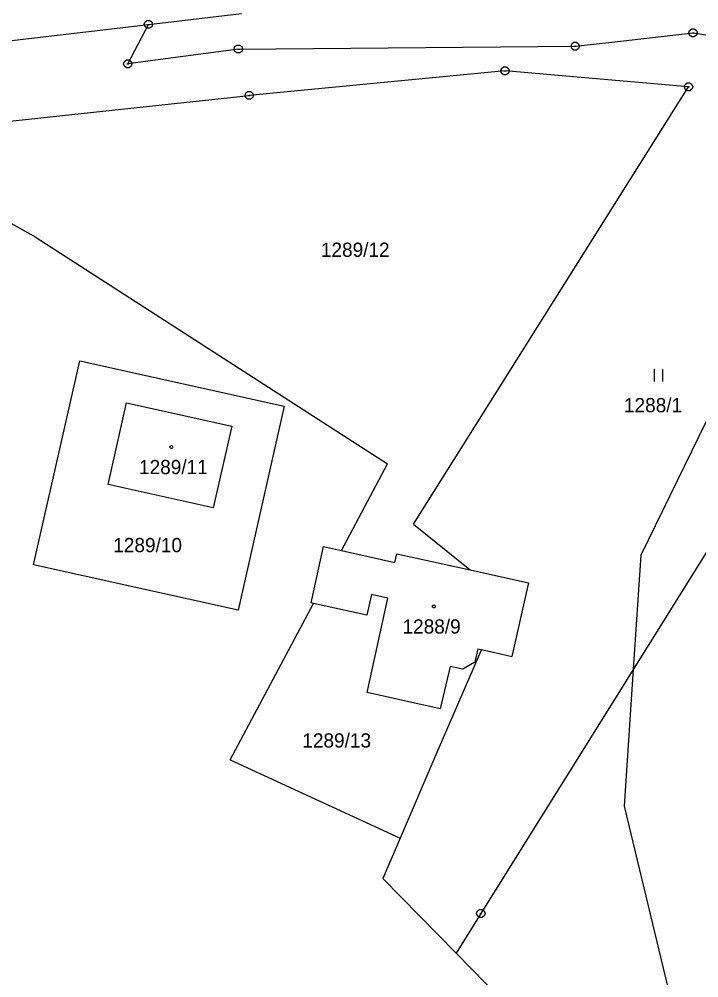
# Model space of a CAD drawing. Extents: x -806774 to -803680, y -1151731 to -1150053.
# Drawn here: x -804399.3 to -804318.1, y -1150598.5 to -1150483.9 of the extents above; entities that cross this region are included whole.
import ezdxf

# ---------------------------------------------------------------- set-up
doc = ezdxf.new("R2010")
doc.units = 0
for name, color, linetype in [('1', 7, 'Continuous'), ('11', 7, 'Continuous'), ('12', 7, 'Continuous'), ('2', 7, 'Continuous'), ('3', 7, 'Continuous'), ('5', 7, 'Continuous'), ('8', 7, 'Continuous')]:
    doc.layers.add(name, color=color, linetype=linetype)

msp = doc.modelspace()

# ---------------------------------------------------------------- linework, layer by layer
at = {"layer": '1'}
for p, q in [((-804383.87, -1150484.55), (-804372.75, -1150483.24)), ((-804413.66, -1150488.07), (-804383.87, -1150484.55)), ((-804386.34, -1150489.27), (-804383.87, -1150484.55)), ((-804328.48, -1150486.67), (-804318.77, -1150485.56)), ((-804318.77, -1150485.56), (-804301.09, -1150488.42)), ((-804332.85, -1150487.17), (-804328.48, -1150486.67)), ((-804373.12, -1150487.5), (-804386.34, -1150489.27)), ((-804373.12, -1150487.5), (-804332.85, -1150487.17)), ((-804341.25, -1150490.12), (-804371.82, -1150493.04)), ((-804330.8, -1150491.03), (-804341.25, -1150490.12)), ((-804319.3, -1150492.03), (-804330.8, -1150491.03)), ((-804352.2, -1150544.3), (-804319.3, -1150492.03)), ((-804282.73, -1150492.43), (-804344.13, -1150590.85)), ((-804389.32, -1150494.92), (-804371.82, -1150493.04)), ((-804418.66, -1150498.07), (-804389.32, -1150494.92)), ((-804397.29, -1150510.02), (-804418.66, -1150498.07)), ((-804397.29, -1150510.02), (-804355.28, -1150537.09)), ((-804397.61, -1150549.18), (-804392.08, -1150524.79)), ((-804392.08, -1150524.79), (-804367.66, -1150530.19)), ((-804388.69, -1150539.57), (-804386.51, -1150529.81)), ((-804386.51, -1150529.81), (-804373.89, -1150532.57)), ((-804367.66, -1150530.19), (-804373.16, -1150554.57)), ((-804373.89, -1150532.57), (-804376.12, -1150542.34)), ((-804360.79, -1150547.46), (-804355.28, -1150537.09)), ((-804376.12, -1150542.34), (-804388.69, -1150539.57)), ((-804352.2, -1150544.3), (-804345.42, -1150549.78)), ((-804364.41, -1150553.72), (-804362.93, -1150546.98)), ((-804362.93, -1150546.98), (-804360.79, -1150547.46)), ((-804360.79, -1150547.46), (-804354.4, -1150548.88)), ((-804354.4, -1150548.88), (-804354.17, -1150547.83)), ((-804354.17, -1150547.83), (-804345.42, -1150549.78)), ((-804373.16, -1150554.57), (-804397.61, -1150549.18)), ((-804345.42, -1150549.78), (-804338.45, -1150551.33)), ((-804338.45, -1150551.33), (-804338.96, -1150553.59)), ((-804357.21, -1150552.7), (-804357.78, -1150555.19)), ((-804357.73, -1150564.42), (-804355.25, -1150553.13)), ((-804355.25, -1150553.13), (-804357.21, -1150552.7)), ((-804374.09, -1150572.48), (-804364.15, -1150553.78)), ((-804364.15, -1150553.78), (-804364.41, -1150553.72)), ((-804357.78, -1150555.19), (-804364.15, -1150553.78)), ((-804338.96, -1150553.59), (-804340.43, -1150560.12)), ((-804344.48, -1150559.2), (-804344.87, -1150560.8)), ((-804344.48, -1150559.2), (-804344.07, -1150559.29)), ((-804344.07, -1150559.29), (-804349.26, -1150571.32)), ((-804344.07, -1150559.29), (-804342.48, -1150559.65)), ((-804342.48, -1150559.65), (-804340.43, -1150560.12)), ((-804347.82, -1150561.33), (-804348.99, -1150566.39)), ((-804346.3, -1150561.65), (-804347.82, -1150561.33)), ((-804344.87, -1150560.8), (-804346.3, -1150561.65)), ((-804348.99, -1150566.39), (-804357.73, -1150564.42)), ((-804349.26, -1150571.32), (-804353.79, -1150581.83)), ((-804374.09, -1150572.48), (-804353.79, -1150581.83)), ((-804353.79, -1150581.83), (-804355.87, -1150586.66)), ((-804355.87, -1150586.66), (-804347.09, -1150595.59)), ((-804344.13, -1150590.85), (-804347.09, -1150595.59)), ((-804347.09, -1150595.59), (-804341.03, -1150601.74))]:
    msp.add_line(p, q, dxfattribs=at)
at = {"layer": '11'}
msp.add_lwpolyline([(-804201.49, -1150551.96), (-804209.11, -1150543.47), (-804210.39, -1150542.04), (-804212.51, -1150539.67), (-804218.5, -1150533), (-804222.87, -1150529.61), (-804225.18, -1150527.81), (-804228.47, -1150525.26), (-804229.6, -1150524.38), (-804232.27, -1150522.31), (-804232.51, -1150522.12), (-804256.88, -1150503.2), (-804257.64, -1150502.61), (-804261, -1150500), (-804264.52, -1150499.82), (-804286.63, -1150498.67), (-804290, -1150498.5), (-804315.5, -1150528.5), (-804325, -1150548), (-804325.91, -1150561.64), (-804327, -1150578), (-804320.5, -1150605)], dxfattribs=at)
at = {"layer": '12'}
for p, q in [((-804388.69, -1150539.57), (-804386.51, -1150529.81)), ((-804386.51, -1150529.81), (-804373.89, -1150532.57)), ((-804373.89, -1150532.57), (-804376.12, -1150542.34)), ((-804376.12, -1150542.34), (-804388.69, -1150539.57)), ((-804364.41, -1150553.72), (-804362.93, -1150546.98)), ((-804362.93, -1150546.98), (-804360.79, -1150547.46)), ((-804360.79, -1150547.46), (-804354.4, -1150548.88)), ((-804354.4, -1150548.88), (-804354.17, -1150547.83)), ((-804354.17, -1150547.83), (-804345.42, -1150549.78)), ((-804345.42, -1150549.78), (-804338.45, -1150551.33)), ((-804338.45, -1150551.33), (-804338.96, -1150553.59)), ((-804357.21, -1150552.7), (-804357.78, -1150555.19)), ((-804357.73, -1150564.42), (-804355.25, -1150553.13)), ((-804355.25, -1150553.13), (-804357.21, -1150552.7)), ((-804364.15, -1150553.78), (-804364.41, -1150553.72)), ((-804357.78, -1150555.19), (-804364.15, -1150553.78)), ((-804338.96, -1150553.59), (-804340.43, -1150560.12)), ((-804344.48, -1150559.2), (-804344.87, -1150560.8)), ((-804344.48, -1150559.2), (-804344.07, -1150559.29)), ((-804344.07, -1150559.29), (-804342.48, -1150559.65)), ((-804342.48, -1150559.65), (-804340.43, -1150560.12)), ((-804347.82, -1150561.33), (-804348.99, -1150566.39)), ((-804346.3, -1150561.65), (-804347.82, -1150561.33)), ((-804344.87, -1150560.8), (-804346.3, -1150561.65)), ((-804348.99, -1150566.39), (-804357.73, -1150564.42))]:
    msp.add_line(p, q, dxfattribs=at)
at = {"layer": '3'}
for p, q in [((-804323.4, -1150525.76), (-804323.4, -1150527.26)), ((-804322.4, -1150527.26), (-804322.4, -1150525.76))]:
    msp.add_line(p, q, dxfattribs=at)
at = {"layer": '5'}
for points in [[(-804381.13, -1150534.91), (-804381.03, -1150534.93), (-804380.98, -1150535.02), (-804380.96, -1150535.08), (-804380.98, -1150535.17), (-804381.06, -1150535.24), (-804381.13, -1150535.25), (-804381.22, -1150535.22), (-804381.28, -1150535.16), (-804381.3, -1150535.08), (-804381.28, -1150534.99), (-804381.2, -1150534.92)], [(-804349.76, -1150553.97), (-804349.66, -1150553.99), (-804349.61, -1150554.08), (-804349.59, -1150554.14), (-804349.61, -1150554.23), (-804349.69, -1150554.3), (-804349.76, -1150554.31), (-804349.85, -1150554.28), (-804349.91, -1150554.22), (-804349.93, -1150554.14), (-804349.91, -1150554.05), (-804349.83, -1150553.98)]]:
    msp.add_lwpolyline(points, close=True, dxfattribs=at)
at = {"layer": '8'}
for p, q in [((-804383.99, -1150484.55), (-804383.75, -1150484.55)), ((-804318.89, -1150485.56), (-804318.65, -1150485.56)), ((-804373.24, -1150487.5), (-804373, -1150487.5)), ((-804332.97, -1150487.17), (-804332.73, -1150487.17)), ((-804386.46, -1150489.27), (-804386.22, -1150489.27)), ((-804341.37, -1150490.12), (-804341.13, -1150490.12)), ((-804319.42, -1150492.03), (-804319.18, -1150492.03)), ((-804371.94, -1150493.04), (-804371.7, -1150493.04)), ((-804344.25, -1150590.85), (-804344.01, -1150590.85))]:
    msp.add_line(p, q, dxfattribs=at)
for points in [[(-804383.72, -1150484.07), (-804383.47, -1150484.25), (-804383.37, -1150484.54), (-804383.47, -1150484.83), (-804383.72, -1150485.01), (-804384.03, -1150485.01), (-804384.28, -1150484.83), (-804384.38, -1150484.54), (-804384.28, -1150484.25), (-804384.03, -1150484.07)], [(-804318.62, -1150485.08), (-804318.37, -1150485.26), (-804318.27, -1150485.55), (-804318.37, -1150485.84), (-804318.62, -1150486.02), (-804318.93, -1150486.02), (-804319.18, -1150485.84), (-804319.28, -1150485.55), (-804319.18, -1150485.26), (-804318.93, -1150485.08)], [(-804372.97, -1150487.02), (-804372.72, -1150487.2), (-804372.62, -1150487.49), (-804372.72, -1150487.78), (-804372.97, -1150487.96), (-804373.28, -1150487.96), (-804373.53, -1150487.78), (-804373.63, -1150487.49), (-804373.53, -1150487.2), (-804373.28, -1150487.02)], [(-804332.7, -1150486.69), (-804332.45, -1150486.87), (-804332.35, -1150487.16), (-804332.45, -1150487.45), (-804332.7, -1150487.63), (-804333.01, -1150487.63), (-804333.26, -1150487.45), (-804333.36, -1150487.16), (-804333.26, -1150486.87), (-804333.01, -1150486.69)], [(-804386.19, -1150488.79), (-804385.94, -1150488.97), (-804385.84, -1150489.26), (-804385.94, -1150489.55), (-804386.19, -1150489.73), (-804386.5, -1150489.73), (-804386.75, -1150489.55), (-804386.85, -1150489.26), (-804386.75, -1150488.97), (-804386.5, -1150488.79)], [(-804341.1, -1150489.64), (-804340.85, -1150489.82), (-804340.75, -1150490.11), (-804340.85, -1150490.4), (-804341.1, -1150490.58), (-804341.41, -1150490.58), (-804341.66, -1150490.4), (-804341.76, -1150490.11), (-804341.66, -1150489.82), (-804341.41, -1150489.64)], [(-804319.15, -1150491.55), (-804318.9, -1150491.73), (-804318.8, -1150492.02), (-804318.9, -1150492.31), (-804319.15, -1150492.49), (-804319.46, -1150492.49), (-804319.71, -1150492.31), (-804319.81, -1150492.02), (-804319.71, -1150491.73), (-804319.46, -1150491.55)], [(-804371.67, -1150492.56), (-804371.42, -1150492.74), (-804371.32, -1150493.03), (-804371.42, -1150493.32), (-804371.67, -1150493.5), (-804371.98, -1150493.5), (-804372.23, -1150493.32), (-804372.33, -1150493.03), (-804372.23, -1150492.74), (-804371.98, -1150492.56)], [(-804343.98, -1150590.37), (-804343.73, -1150590.55), (-804343.63, -1150590.84), (-804343.73, -1150591.13), (-804343.98, -1150591.31), (-804344.29, -1150591.31), (-804344.54, -1150591.13), (-804344.64, -1150590.84), (-804344.54, -1150590.55), (-804344.29, -1150590.37)]]:
    msp.add_lwpolyline(points, close=True, dxfattribs=at)

# ---------------------------------------------------------------- texts
at = {"layer": '2'}
for s, p in [('1289/12', (-804363.26, -1150512.34)), ('1288/1', (-804327.03, -1150530.92)), ('1289/11', (-804385, -1150538.32)), ('1289/10', (-804388.08, -1150547.65)), ('1288/9', (-804353.5, -1150557.38)), ('1289/13', (-804365.48, -1150571.01))]:
    msp.add_text(s, height=1.7, dxfattribs=at).set_placement(p)

doc.saveas('drawing.dxf')
